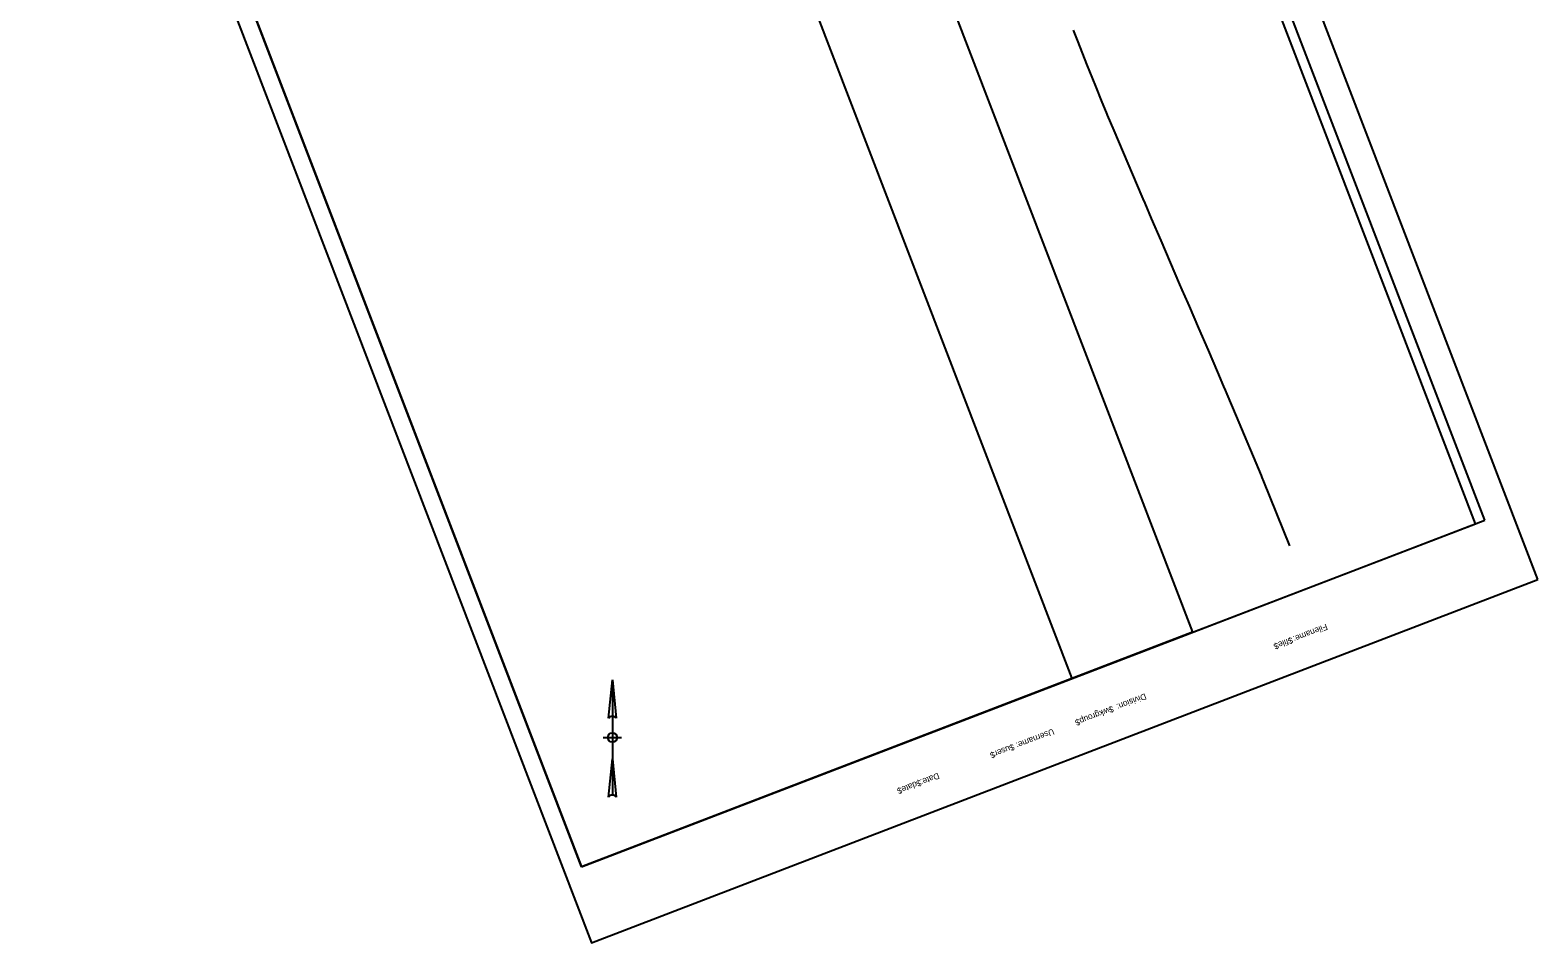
# Model space of a CAD drawing. Extents: x 1037816 to 1038634, y 779660 to 780651.
# Drawn here: x 1037816 to 1038634, y 779660 to 780155 of the extents above; entities that cross this region are included whole.
import ezdxf

# ---------------------------------------------------------------- set-up
doc = ezdxf.new("R2010")
doc.units = 0
for name, color, linetype in [('CLIPS', 7, 'Continuous'), ('Default', 7, 'Continuous'), ('PLOT BOUNDARY', 7, 'Continuous'), ('S_Roadway_Centerline', 7, 'Continuous')]:
    doc.layers.add(name, color=color, linetype=linetype)

msp = doc.modelspace()

# ---------------------------------------------------------------- linework, layer by layer
at = {"layer": 'CLIPS'}
for points in [[(1038600.29, 779887.43), (1038331.52, 780587.61), (1038112.49, 780503.53), (1038381.26, 779803.35)], [(1038115.24, 779701.23), (1037846.46, 780401.42), (1038178.05, 780528.7), (1038446.83, 779828.52)]]:
    msp.add_lwpolyline(points, close=True, dxfattribs=at)
at = {"layer": 'Default'}
for p, q in [((1038605.37, 779889.37), (1038318.67, 780636.24)), ((1037828.54, 780448.09), (1038115.24, 779701.23)), ((1038115.24, 779701.23), (1038605.37, 779889.37)), ((1038129.93, 779781.82), (1038132.02, 779802.66)), ((1038132.02, 779802.66), (1038132.02, 779740.16)), ((1038132.02, 779802.66), (1038134.1, 779781.82)), ((1038127.02, 779771.41), (1038137.02, 779771.41)), ((1038129.93, 779739.04), (1038132.02, 779759.87)), ((1038132.02, 779759.87), (1038134.1, 779739.04))]:
    msp.add_line(p, q, dxfattribs=at)
msp.add_circle((1038132.02, 779771.41), 2.5, dxfattribs=at)
for centre in [(1038132.02, 779780.44), (1038132.02, 779737.66)]:
    msp.add_arc(centre, 2.5, 33.55731, 146.44269, dxfattribs=at)
at = {"layer": 'PLOT BOUNDARY'}
msp.add_lwpolyline([(1038634.15, 779857.08), (1038329.54, 780650.62), (1037816.07, 780453.52), (1038120.68, 779659.97)], close=True, dxfattribs=at)
at = {"layer": 'S_Roadway_Centerline'}
msp.add_lwpolyline([(1038499.6, 779875.51), (1038485.4, 779910.41), (1038484.55, 779912.57), (1038484.19, 779913.56), (1038470.64, 779945.85), (1038465.62, 779957.81), (1038464.73, 779959.9), (1038463.82, 779961.98), (1038460.51, 779969.71), (1038455.38, 779981.63), (1038450.23, 779993.53), (1038445.08, 780005.44), (1038444.33, 780007.15), (1038442.79, 780010.68), (1038441.12, 780014.43), (1038439.89, 780017.34), (1038434.8, 780029.28), (1038429.71, 780041.2), (1038424.6, 780053.12), (1038421.08, 780061.33), (1038420.04, 780063.71), (1038419.47, 780065.05), (1038414.4, 780076.99), (1038409.33, 780088.92), (1038404.24, 780100.85), (1038400.73, 780109.08), (1038400.49, 780109.64), (1038399.18, 780112.82), (1038397.77, 780116.23), (1038394.31, 780124.86), (1038389.5, 780136.9), (1038384.72, 780148.95), (1038382.2, 780155.3)], dxfattribs=at)

# ---------------------------------------------------------------- texts
at = {"layer": 'Default'}
for s, p in [('Filename:', (1038519.28, 779833.22)), ('$file$', (1038500.48, 779826)), ('Division:', (1038420.94, 779795.47)), ('$wkgroup$', (1038403.19, 779788.65)), ('Username:', (1038370.99, 779776.29)), ('$user$', (1038349.4, 779768.01)), ('$date$', (1038298.93, 779748.63)), ('Date:', (1038308.67, 779752.37))]:
    msp.add_text(s, height=3.348, rotation=201, dxfattribs=at).set_placement(p)

doc.saveas('drawing.dxf')
